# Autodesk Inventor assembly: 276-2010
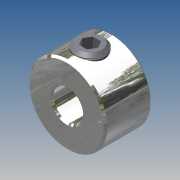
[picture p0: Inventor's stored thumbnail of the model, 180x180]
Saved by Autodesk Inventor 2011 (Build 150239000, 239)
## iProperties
Company: Autodesk Inc.
Created: 2010-06
Document SubType Name: Assembly
Designer: Autodesk Inc.
Part Number: 276-2010
Catalog Web Link: http://www.vexrobotics.com/276-2010.html
Description: Collars lock to drive shafts, keeping wheels and gears from sliding along the shaft.
Vendor: Innovation First, Inc.
Author: Autodesk Inc.
Title: VEX Robotics Kit of Parts
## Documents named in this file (3)
- C:\Data Folder\VEX KOP 2010\Shaft Collar.iam
- C:\Data Folder\VEX KOP 2010\Shaft Collar.ipt
- C:\Users\Phil\Documents\Inventor\Content Center Files\R2011\en-US\ANSI B18.3(20)\ANSI B18.3 - 8-32 UNC - 0.1875(32)306.ipt
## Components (2 placed, 2 different names)
1. Shaft Collar:1 — Mate:1, Flush:1, Angle:1
2. Type B - Hexagon Socket Set Screw - Cup Point - Inch 8-32 UNC - 0.1875:1 — Mate:1, Flush:1, Angle:1
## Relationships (3: Mate 1, Flush 1, Angle 1)
- Mate:1: Shaft Collar:1 ↔ Type B - Hexagon Socket Set Screw - Cup Point - Inch 8-32 UNC - 0.1875:1
- Flush:1: Shaft Collar:1 ↔ Type B - Hexagon Socket Set Screw - Cup Point - Inch 8-32 UNC - 0.1875:1
- Angle:1: Shaft Collar:1 ↔ Type B - Hexagon Socket Set Screw - Cup Point - Inch 8-32 UNC - 0.1875:1
